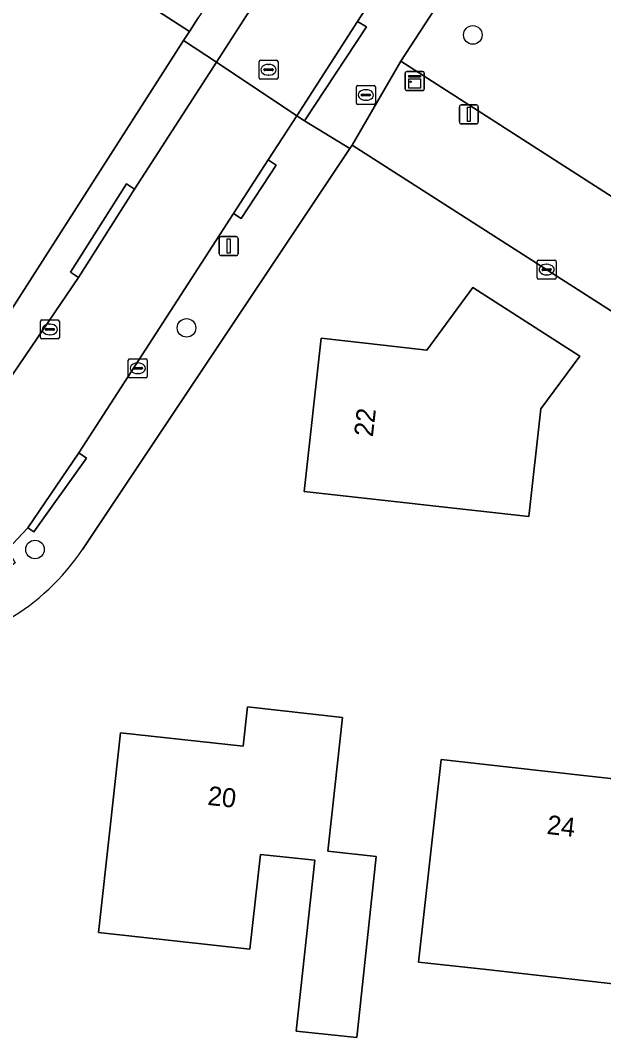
# Model space of a CAD drawing. Extents: x 162396 to 163643, y 386452 to 387406.
# Drawn here: x 163145.4 to 163176.1, y 386547 to 386600.6 of the extents above; entities that cross this region are included whole.
import ezdxf

# ---------------------------------------------------------------- set-up
doc = ezdxf.new("R2010")
doc.units = 0
for name, color, linetype in [('IMGEO_Boom', 7, 'Continuous'), ('IMGEO_Brandkraan', 7, 'Continuous'), ('IMGEO_Erf', 7, 'Continuous'), ('IMGEO_Groenvoorziening', 7, 'Continuous'), ('IMGEO_Kast', 7, 'Continuous'), ('IMGEO_Kolk', 7, 'Continuous'), ('IMGEO_Lichtmast', 7, 'Continuous'), ('IMGEO_Pand', 7, 'Continuous'), ('IMGEO_Pand_nummerreeks', 7, 'Continuous'), ('IMGEO_Rijbaan_lokaal_open', 7, 'Continuous'), ('IMGEO_Rioolput', 7, 'Continuous'), ('IMGEO_Voetpad_open', 7, 'Continuous')]:
    doc.layers.add(name, color=color, linetype=linetype)

msp = doc.modelspace()

# ---------------------------------------------------------------- linework, layer by layer
at = {"layer": 'IMGEO_Boom'}
for centre in [(163169.216, 386599.866), (163154.148, 386584.433), (163146.17, 386572.761)]:
    msp.add_circle(centre, 0.489, dxfattribs=at)
at = {"layer": 'IMGEO_Brandkraan'}
for p, q in [((163163.088, 386596.275), (163163.088, 386597.127)), ((163163.163, 386597.201), (163164.015, 386597.201)), ((163163.576, 386596.981), (163163.601, 386596.981)), ((163164.089, 386597.127), (163164.089, 386596.275)), ((163163.347, 386596.695), (163163.347, 386596.707)), ((163163.785, 386596.658), (163163.387, 386596.658)), ((163163.39, 386596.744), (163163.788, 386596.744)), ((163163.599, 386596.421), (163163.574, 386596.421)), ((163163.831, 386596.707), (163163.831, 386596.695)), ((163164.015, 386596.201), (163163.163, 386596.201))]:
    msp.add_line(p, q, dxfattribs=at)
for points in [[(163163.088, 386596.275), (163163.088, 386597.127)], [(163163.163, 386597.201), (163164.015, 386597.201)], [(163164.089, 386597.127), (163164.089, 386596.275)], [(163164.015, 386596.201), (163163.163, 386596.201)]]:
    msp.add_lwpolyline(points, dxfattribs=at)
for centre, radius, start, end in [((163163.165, 386597.125), 0.0765, 91.552, 178.448), ((163163.165, 386597.125), 0.0765, 91.552, 178.448), ((163164.013, 386597.125), 0.0765, 1.552, 88.448), ((163164.013, 386597.125), 0.0765, 1.552, 88.448), ((163163.165, 386596.277), 0.0765, 181.552, 268.448), ((163163.165, 386596.277), 0.0765, 181.552, 268.448), ((163163.387, 386596.704), 0.0403, 85.8775, 175.7526), ((163163.384, 386596.694), 0.0366, 178.938, 274.7102), ((163163.788, 386596.701), 0.043, 264.8664, 352.4533), ((163163.792, 386596.706), 0.0386, 1.7309, 96.639), ((163164.013, 386596.277), 0.0765, 271.552, 358.448), ((163164.013, 386596.277), 0.0765, 271.552, 358.448)]:
    msp.add_arc(centre, radius, start, end, dxfattribs=at)
for centre, major_axis, ratio, start_param, end_param in [((163163.575, 386596.701), (-0.387, 0.002), 0.722429, 4.712389, 7.853982), ((163163.6, 386596.701), (-0.39, 0.002), 0.717154, 1.570796, 4.712389)]:
    msp.add_ellipse(centre, major_axis=major_axis, ratio=ratio, start_param=start_param, end_param=end_param, dxfattribs=at)
at = {"layer": 'IMGEO_Erf'}
for points in [[(163153.99, 386599.564), (163154.3, 386600.048), (163147.369, 386604.55), (163132.249, 386614.371), (163098.967, 386635.988), (163097.29, 386637.077), (163090.42, 386575.726)], [(163140.254, 386578.096), (163153.99, 386599.564)], [(163219.905, 386556.9), (163215.727, 386559.453), (163210.744, 386563.528), (163208.288, 386563.796), (163179.455, 386566.945), (163181.339, 386582.22), (163162.868, 386594.067), (163162.747, 386593.885), (163148.669, 386572.762)]]:
    msp.add_lwpolyline(points, dxfattribs=at)
for points in [[(163161.239, 386583.887), (163164.491, 386583.522), (163166.795, 386583.264), (163169.22, 386586.553), (163174.842, 386582.948), (163172.794, 386580.17), (163172.157, 386574.494), (163160.334, 386575.82)], [(163149.516, 386552.585), (163150.126, 386558.138), (163150.671, 386563.108), (163157.121, 386562.4), (163157.348, 386564.464), (163162.352, 386563.915), (163161.806, 386558.945), (163161.578, 386556.866), (163164.13, 386556.586), (163163.104, 386547.044), (163159.913, 386547.394), (163160.901, 386556.385), (163158.033, 386556.7), (163157.486, 386551.71)], [(163169.939, 386550.628), (163166.36, 386551.027), (163167.544, 386561.698), (163171.13, 386561.297), (163177.39, 386560.599), (163177.287, 386559.674), (163179.062, 386559.476), (163179.42, 386562.686), (163184.674, 386562.1), (163184.12, 386557.131), (163183.087, 386547.877), (163176.922, 386548.565), (163177.064, 386549.833)]]:
    msp.add_lwpolyline(points, close=True, dxfattribs=at)
msp.add_arc((163138.688, 386579.413), 11.994, 274.4362, 326.3227, dxfattribs=at)
at = {"layer": 'IMGEO_Groenvoorziening'}
msp.add_lwpolyline([(163184.479, 386604.445), (163174.056, 386608.85), (163172.55, 386609.437), (163165.428, 386598.489), (163176.603, 386591.3), (163193.76, 386598.435), (163195.039, 386598.967), (163194.839, 386600.067)], close=True, dxfattribs=at)
msp.add_lwpolyline([(163147.369, 386604.55), (163154.3, 386600.048), (163154.767, 386600.758)], dxfattribs=at)
at = {"layer": 'IMGEO_Kast'}
for p, q in [((163165.659, 386597.008), (163165.659, 386597.849)), ((163165.659, 386597.849), (163165.659, 386597.008)), ((163165.734, 386597.933), (163166.575, 386597.933)), ((163166.575, 386597.933), (163165.734, 386597.933)), ((163166.659, 386597.858), (163166.659, 386597.017)), ((163166.659, 386597.017), (163166.659, 386597.858)), ((163166.584, 386596.933), (163165.743, 386596.933)), ((163165.743, 386596.933), (163166.584, 386596.933))]:
    msp.add_line(p, q, dxfattribs=at)
for points in [[(163165.854, 386597.723), (163166.454, 386597.723), (163166.454, 386597.638), (163165.854, 386597.638), (163165.854, 386597.723)], [(163165.854, 386597.548), (163166.454, 386597.548), (163166.454, 386597.059), (163165.854, 386597.059), (163165.854, 386597.548)]]:
    msp.add_lwpolyline(points, dxfattribs=at)
msp.add_circle((163165.938, 386597.397), 0.0377, dxfattribs=at)
for centre, start, end in [((163165.737, 386597.855), 92.4484, 184.2845), ((163165.737, 386597.855), 92.4484, 184.2845), ((163166.581, 386597.855), 2.4484, 94.2845), ((163166.581, 386597.855), 2.4484, 94.2845), ((163165.737, 386597.011), 182.4484, 274.2845), ((163165.737, 386597.011), 182.4484, 274.2845), ((163166.581, 386597.011), 272.4484, 4.2845), ((163166.581, 386597.011), 272.4484, 4.2845)]:
    msp.add_arc(centre, 0.0779, start, end, dxfattribs=at)
at = {"layer": 'IMGEO_Kolk'}
for p, q in [((163172.603, 386587.078), (163172.603, 386587.93)), ((163172.678, 386588.004), (163173.53, 386588.004)), ((163173.091, 386587.784), (163173.116, 386587.784)), ((163173.604, 386587.93), (163173.604, 386587.078)), ((163172.862, 386587.498), (163172.862, 386587.51)), ((163173.3, 386587.461), (163172.902, 386587.461)), ((163172.905, 386587.547), (163173.303, 386587.547)), ((163173.114, 386587.224), (163173.089, 386587.224)), ((163173.346, 386587.51), (163173.346, 386587.498)), ((163173.53, 386587.004), (163172.678, 386587.004)), ((163146.455, 386583.925), (163146.455, 386584.777)), ((163146.53, 386584.851), (163147.382, 386584.851)), ((163146.943, 386584.631), (163146.968, 386584.631)), ((163147.456, 386584.777), (163147.456, 386583.925)), ((163146.714, 386584.345), (163146.714, 386584.357)), ((163147.152, 386584.308), (163146.754, 386584.308)), ((163146.757, 386584.394), (163147.155, 386584.394)), ((163146.966, 386584.071), (163146.941, 386584.071)), ((163147.198, 386584.357), (163147.198, 386584.345)), ((163147.382, 386583.851), (163146.53, 386583.851)), ((163151.082, 386581.879), (163151.082, 386582.731)), ((163151.157, 386582.805), (163152.009, 386582.805)), ((163151.341, 386582.299), (163151.341, 386582.311)), ((163151.384, 386582.348), (163151.782, 386582.348)), ((163151.57, 386582.585), (163151.595, 386582.585)), ((163151.825, 386582.311), (163151.825, 386582.299)), ((163152.083, 386582.731), (163152.083, 386581.879)), ((163152.009, 386581.805), (163151.157, 386581.805)), ((163151.779, 386582.262), (163151.381, 386582.262)), ((163151.593, 386582.025), (163151.568, 386582.025))]:
    msp.add_line(p, q, dxfattribs=at)
for points in [[(163172.603, 386587.078), (163172.603, 386587.93)], [(163172.678, 386588.004), (163173.53, 386588.004)], [(163173.604, 386587.93), (163173.604, 386587.078)], [(163173.53, 386587.004), (163172.678, 386587.004)], [(163146.455, 386583.925), (163146.455, 386584.777)], [(163146.53, 386584.851), (163147.382, 386584.851)], [(163147.456, 386584.777), (163147.456, 386583.925)], [(163147.382, 386583.851), (163146.53, 386583.851)], [(163151.082, 386581.879), (163151.082, 386582.731)], [(163151.157, 386582.805), (163152.009, 386582.805)], [(163152.083, 386582.731), (163152.083, 386581.879)], [(163152.009, 386581.805), (163151.157, 386581.805)]]:
    msp.add_lwpolyline(points, dxfattribs=at)
for centre, radius, start, end in [((163172.68, 386587.928), 0.0765, 91.552, 178.448), ((163172.68, 386587.928), 0.0765, 91.552, 178.448), ((163173.528, 386587.928), 0.0765, 1.552, 88.448), ((163173.528, 386587.928), 0.0765, 1.552, 88.448), ((163172.902, 386587.507), 0.0403, 85.8775, 175.7526), ((163172.899, 386587.497), 0.0366, 178.938, 274.7102), ((163173.303, 386587.504), 0.043, 264.8664, 352.4533), ((163173.307, 386587.509), 0.0386, 1.7309, 96.639), ((163172.68, 386587.08), 0.0765, 181.552, 268.448), ((163172.68, 386587.08), 0.0765, 181.552, 268.448), ((163173.528, 386587.08), 0.0765, 271.552, 358.448), ((163173.528, 386587.08), 0.0765, 271.552, 358.448), ((163146.532, 386584.775), 0.0765, 91.552, 178.448), ((163146.532, 386584.775), 0.0765, 91.552, 178.448), ((163147.38, 386584.775), 0.0765, 1.552, 88.448), ((163147.38, 386584.775), 0.0765, 1.552, 88.448), ((163146.532, 386583.927), 0.0765, 181.552, 268.448), ((163146.532, 386583.927), 0.0765, 181.552, 268.448), ((163146.754, 386584.354), 0.0403, 85.8775, 175.7526), ((163146.751, 386584.344), 0.0366, 178.938, 274.7102), ((163147.155, 386584.351), 0.043, 264.8664, 352.4533), ((163147.159, 386584.356), 0.0386, 1.7309, 96.639), ((163147.38, 386583.927), 0.0765, 271.552, 358.448), ((163147.38, 386583.927), 0.0765, 271.552, 358.448), ((163151.159, 386582.729), 0.0765, 91.552, 178.448), ((163151.159, 386582.729), 0.0765, 91.552, 178.448), ((163151.381, 386582.308), 0.0403, 85.8775, 175.7526), ((163151.786, 386582.31), 0.0386, 1.7309, 96.639), ((163152.007, 386582.729), 0.0765, 1.552, 88.448), ((163152.007, 386582.729), 0.0765, 1.552, 88.448), ((163151.159, 386581.881), 0.0765, 181.552, 268.448), ((163151.159, 386581.881), 0.0765, 181.552, 268.448), ((163151.378, 386582.298), 0.0366, 178.938, 274.7102), ((163151.782, 386582.305), 0.043, 264.8664, 352.4533), ((163152.007, 386581.881), 0.0765, 271.552, 358.448), ((163152.007, 386581.881), 0.0765, 271.552, 358.448)]:
    msp.add_arc(centre, radius, start, end, dxfattribs=at)
for centre, major_axis, ratio, start_param, end_param in [((163173.09, 386587.504), (-0.387, 0.002), 0.722429, 4.712389, 7.853982), ((163173.115, 386587.504), (-0.39, 0.002), 0.717154, 1.570796, 4.712389), ((163146.942, 386584.351), (-0.387, 0.002), 0.722429, 4.712389, 7.853982), ((163146.967, 386584.351), (-0.39, 0.002), 0.717154, 1.570796, 4.712389), ((163151.569, 386582.305), (-0.387, 0.002), 0.722429, 4.712389, 7.853982), ((163151.594, 386582.305), (-0.39, 0.002), 0.717154, 1.570796, 4.712389)]:
    msp.add_ellipse(centre, major_axis=major_axis, ratio=ratio, start_param=start_param, end_param=end_param, dxfattribs=at)
at = {"layer": 'IMGEO_Lichtmast'}
for p, q in [((163168.511, 386595.28), (163168.511, 386596.08)), ((163168.511, 386596.08), (163168.511, 386595.28)), ((163168.611, 386596.18), (163169.401, 386596.18)), ((163169.401, 386596.18), (163168.611, 386596.18)), ((163169.501, 386596.08), (163169.501, 386595.28)), ((163169.501, 386595.28), (163169.501, 386596.08)), ((163169.401, 386595.18), (163168.611, 386595.18)), ((163168.611, 386595.18), (163169.401, 386595.18)), ((163155.873, 386588.343), (163155.873, 386589.143)), ((163155.873, 386589.143), (163155.873, 386588.343)), ((163155.973, 386589.243), (163156.763, 386589.243)), ((163156.763, 386589.243), (163155.973, 386589.243)), ((163156.863, 386589.143), (163156.863, 386588.343)), ((163156.863, 386588.343), (163156.863, 386589.143)), ((163156.763, 386588.243), (163155.973, 386588.243)), ((163155.973, 386588.243), (163156.763, 386588.243))]:
    msp.add_line(p, q, dxfattribs=at)
for points in [[(163168.931, 386596.055), (163169.081, 386596.055), (163169.081, 386595.305), (163168.931, 386595.305), (163168.931, 386596.055)], [(163156.293, 386589.118), (163156.443, 386589.118), (163156.443, 386588.368), (163156.293, 386588.368), (163156.293, 386589.118)]]:
    msp.add_lwpolyline(points, dxfattribs=at)
for centre, start, end in [((163168.611, 386596.08), 90, 180), ((163168.611, 386596.08), 90, 180), ((163169.401, 386596.08), 0, 90), ((163169.401, 386596.08), 360, 90), ((163168.611, 386595.28), 180, 270), ((163168.611, 386595.28), 180, 270), ((163169.401, 386595.28), 270, 0), ((163169.401, 386595.28), 270, 0), ((163155.973, 386589.143), 90, 180), ((163155.973, 386589.143), 90, 180), ((163156.763, 386589.143), 0, 90), ((163156.763, 386589.143), 360, 90), ((163155.973, 386588.343), 180, 270), ((163155.973, 386588.343), 180, 270), ((163156.763, 386588.343), 270, 0), ((163156.763, 386588.343), 270, 0)]:
    msp.add_arc(centre, 0.1, start, end, dxfattribs=at)
at = {"layer": 'IMGEO_Pand'}
for points in [[(163161.239, 386583.887), (163160.334, 386575.82), (163172.157, 386574.494), (163172.794, 386580.17), (163174.842, 386582.948), (163169.22, 386586.553), (163166.795, 386583.264), (163164.491, 386583.522)], [(163149.516, 386552.585), (163157.486, 386551.71), (163158.033, 386556.7), (163160.901, 386556.385), (163159.913, 386547.394), (163163.104, 386547.044), (163164.13, 386556.586), (163161.578, 386556.866), (163161.806, 386558.945), (163162.352, 386563.915), (163157.348, 386564.464), (163157.121, 386562.4), (163150.671, 386563.108), (163150.126, 386558.138)], [(163171.13, 386561.297), (163167.544, 386561.698), (163166.36, 386551.027), (163169.939, 386550.628), (163177.064, 386549.833), (163176.922, 386548.565), (163183.087, 386547.877), (163184.12, 386557.131), (163184.674, 386562.1), (163179.42, 386562.686), (163179.062, 386559.476), (163177.287, 386559.674), (163177.39, 386560.599)]]:
    msp.add_lwpolyline(points, close=True, dxfattribs=at)
at = {"layer": 'IMGEO_Rijbaan_lokaal_open'}
for points in [[(163170.383, 386621.063), (163157.309, 386600.896), (163155.72, 386598.432), (163159.947, 386595.608), (163163.152, 386600.57), (163171.211, 386613.025), (163173.217, 386616.053)], [(163145.792, 386573.901), (163148.476, 386577.85), (163156.613, 386590.462), (163158.448, 386593.281), (163159.947, 386595.608), (163155.72, 386598.432), (163151.409, 386591.748), (163148.456, 386587.094), (163141.904, 386577.447)], [(163020.857, 386561.073), (163036.802, 386562.095), (163040.949, 386562.483), (163054.314, 386563.512), (163060.944, 386564.22), (163074.412, 386565.159), (163081.812, 386565.794), (163084.079, 386565.981), (163087.793, 386566.294), (163096.974, 386566.98), (163101.964, 386567.36), (163118.7, 386568.695), (163124.883, 386569.21), (163138.986, 386570.276), (163139.978, 386570.426), (163141.507, 386570.918), (163142.286, 386571.231), (163142.946, 386571.563), (163143.618, 386571.936), (163144.218, 386572.324), (163144.729, 386572.764), (163145.792, 386573.901)]]:
    msp.add_lwpolyline(points, dxfattribs=at)
at = {"layer": 'IMGEO_Rioolput'}
for p, q in [((163157.963, 386597.605), (163157.963, 386598.457)), ((163158.038, 386598.531), (163158.89, 386598.531)), ((163158.964, 386598.457), (163158.964, 386597.605)), ((163158.222, 386598.025), (163158.222, 386598.037)), ((163158.66, 386597.988), (163158.262, 386597.988)), ((163158.265, 386598.074), (163158.663, 386598.074)), ((163158.451, 386598.311), (163158.476, 386598.311)), ((163158.706, 386598.037), (163158.706, 386598.025)), ((163158.89, 386597.531), (163158.038, 386597.531)), ((163158.474, 386597.751), (163158.449, 386597.751))]:
    msp.add_line(p, q, dxfattribs=at)
for points in [[(163157.963, 386597.605), (163157.963, 386598.457)], [(163158.038, 386598.531), (163158.89, 386598.531)], [(163158.964, 386598.457), (163158.964, 386597.605)], [(163158.89, 386597.531), (163158.038, 386597.531)]]:
    msp.add_lwpolyline(points, dxfattribs=at)
for centre, radius, start, end in [((163158.04, 386598.455), 0.0765, 91.552, 178.448), ((163158.04, 386598.455), 0.0765, 91.552, 178.448), ((163158.888, 386598.455), 0.0765, 1.552, 88.448), ((163158.888, 386598.455), 0.0765, 1.552, 88.448), ((163158.262, 386598.034), 0.0403, 85.8775, 175.7526), ((163158.259, 386598.024), 0.0366, 178.938, 274.7102), ((163158.663, 386598.031), 0.043, 264.8664, 352.4533), ((163158.667, 386598.036), 0.0386, 1.7309, 96.639), ((163158.04, 386597.607), 0.0765, 181.552, 268.448), ((163158.04, 386597.607), 0.0765, 181.552, 268.448), ((163158.888, 386597.607), 0.0765, 271.552, 358.448), ((163158.888, 386597.607), 0.0765, 271.552, 358.448)]:
    msp.add_arc(centre, radius, start, end, dxfattribs=at)
for centre, major_axis, ratio, start_param, end_param in [((163158.45, 386598.031), (-0.387, 0.002), 0.722429, 4.712389, 7.853982), ((163158.475, 386598.031), (-0.39, 0.002), 0.717154, 1.570796, 4.712389)]:
    msp.add_ellipse(centre, major_axis=major_axis, ratio=ratio, start_param=start_param, end_param=end_param, dxfattribs=at)
at = {"layer": 'IMGEO_Voetpad_open'}
for points in [[(163170.774, 386633.603), (163169.693, 386624.27), (163169.53, 386624.376), (163169.473, 386623.808), (163168.877, 386622.376), (163165.325, 386616.866), (163158.876, 386606.957), (163157.847, 386605.38), (163154.767, 386600.758), (163154.3, 386600.048), (163153.99, 386599.564), (163155.72, 386598.432), (163157.309, 386600.896), (163170.383, 386621.063)], [(163173.217, 386616.053), (163171.211, 386613.025), (163163.152, 386600.57), (163163.622, 386600.3), (163160.363, 386595.333), (163162.747, 386593.885), (163162.868, 386594.067), (163165.428, 386598.489), (163172.55, 386609.437), (163174.056, 386608.85), (163175.119, 386610.507), (163175.187, 386610.613), (163174.47, 386610.927), (163173.889, 386611.181), (163173.944, 386611.267), (163175.6, 386613.85)], [(163155.72, 386598.432), (163153.99, 386599.564), (163140.254, 386578.096)], [(163141.904, 386577.447), (163148.456, 386587.094), (163148.038, 386587.368), (163150.991, 386592.022), (163151.409, 386591.748), (163155.72, 386598.432)], [(163148.669, 386572.762), (163162.747, 386593.885), (163160.363, 386595.333), (163159.947, 386595.608), (163158.448, 386593.281), (163158.864, 386593.006), (163157.029, 386590.187), (163156.613, 386590.462), (163148.476, 386577.85), (163148.887, 386577.566), (163146.104, 386573.69), (163145.792, 386573.901), (163144.729, 386572.764), (163145.121, 386572.056), (163144.342, 386571.445), (163142.219, 386570.544), (163140.082, 386569.938), (163139.978, 386570.426), (163138.986, 386570.276), (163124.883, 386569.21), (163124.919, 386568.712), (163118.736, 386568.197), (163118.7, 386568.695), (163101.964, 386567.36)]]:
    msp.add_lwpolyline(points, dxfattribs=at)
for points in [[(163163.622, 386600.3), (163163.152, 386600.57), (163159.947, 386595.608), (163160.363, 386595.333)], [(163180.6, 386588.781), (163178.562, 386590.099), (163176.603, 386591.3), (163165.428, 386598.489), (163162.868, 386594.067), (163181.339, 386582.22), (163179.455, 386566.945), (163208.288, 386563.796), (163209.046, 386570.411), (163204.928, 386573.048)], [(163158.864, 386593.006), (163158.448, 386593.281), (163156.613, 386590.462), (163157.029, 386590.187)], [(163151.409, 386591.748), (163150.991, 386592.022), (163148.038, 386587.368), (163148.456, 386587.094)], [(163148.887, 386577.566), (163148.476, 386577.85), (163145.792, 386573.901), (163146.104, 386573.69)]]:
    msp.add_lwpolyline(points, close=True, dxfattribs=at)
msp.add_arc((163138.688, 386579.413), 11.994, 274.4362, 326.3227, dxfattribs=at)

# ---------------------------------------------------------------- texts
at = {"layer": 'IMGEO_Pand_nummerreeks'}
for s, rotation, p in [('22', 83.599, (163163.953, 386578.664)), ('20', 353.7359, (163155.222, 386559.309)), ('24', 353.6377, (163173.076, 386557.78))]:
    msp.add_text(s, height=1, rotation=rotation, dxfattribs=at).set_placement(p)

doc.saveas('drawing.dxf')
